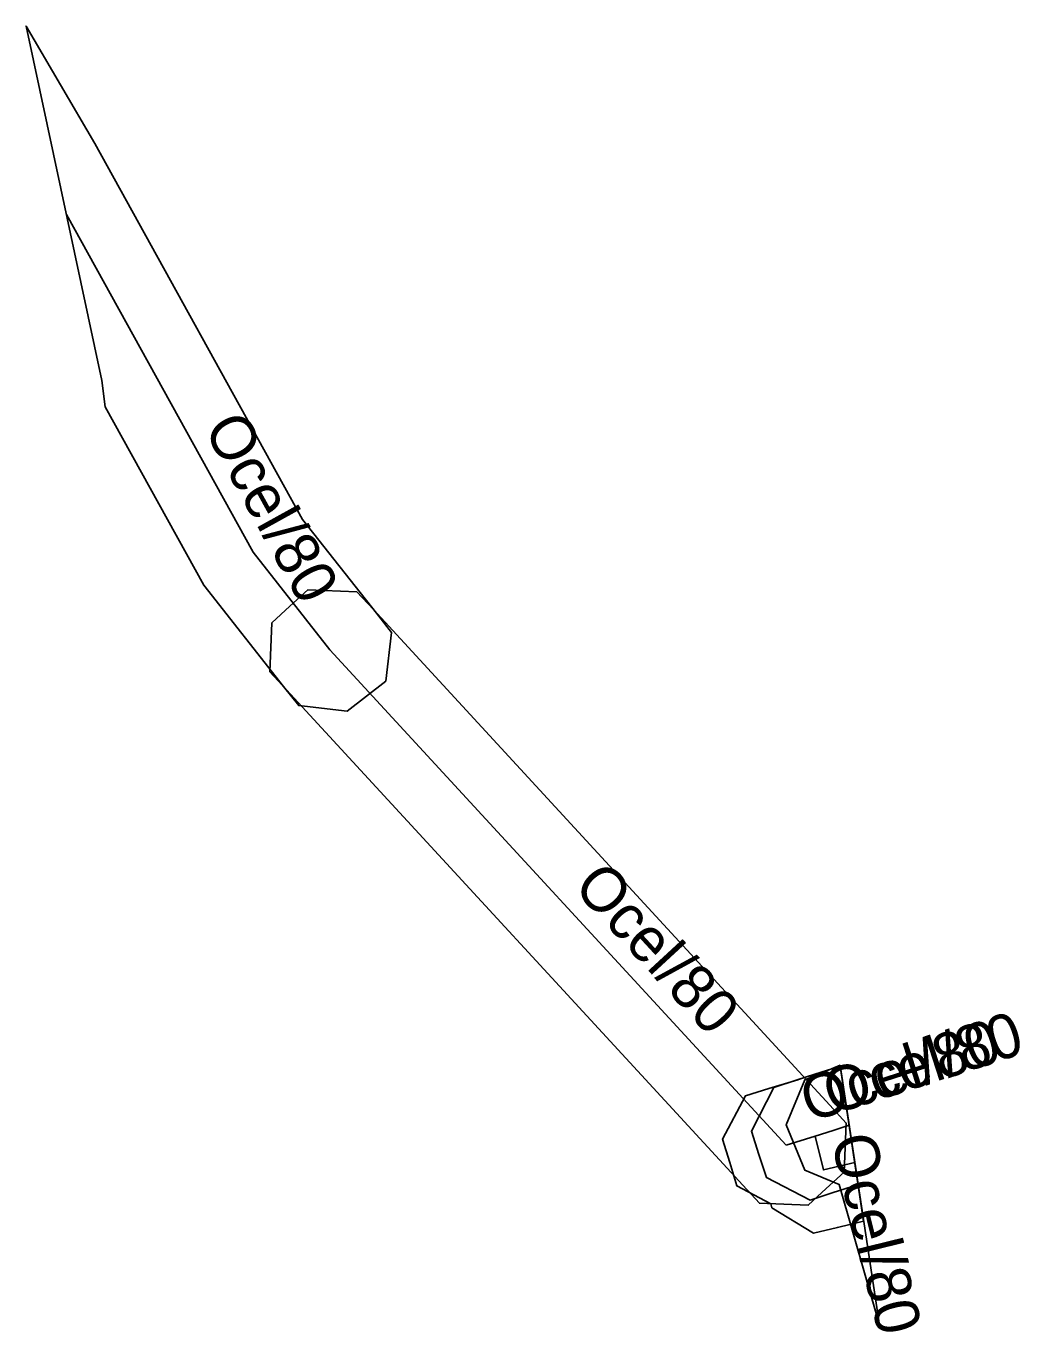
# Model space of a CAD drawing. Extents: x -569518 to -569136, y -1179473 to -1178304.
# Drawn here: x -569153.14 to -569136.31, y -1178325.81 to -1178303.7 of the extents above; entities that cross this region are included whole.
import ezdxf

# ---------------------------------------------------------------- set-up
doc = ezdxf.new("R2010")
doc.units = 0
for name, color, linetype in [('1', 7, 'Continuous'), ('24', 7, 'Continuous'), ('30', 7, 'Continuous')]:
    doc.layers.add(name, color=color, linetype=linetype)

msp = doc.modelspace()

# ---------------------------------------------------------------- linework, layer by layer
at = {"layer": '1'}
for points in [[(-569151.859, -1178309.697), (-569153.141, -1178303.701), (-569151.981, -1178305.686), (-569148.464, -1178312.045), (-569147.215, -1178313.631), (-569146.959, -1178313.957), (-569147.056, -1178314.779), (-569147.381, -1178315.035), (-569147.707, -1178315.291), (-569148.529, -1178315.194), (-569148.785, -1178314.869), (-569150.136, -1178313.155), (-569151.803, -1178310.14)], [(-569147.545, -1178313.268), (-569147.265, -1178313.572), (-569139.545, -1178321.952), (-569139.264, -1178322.257), (-569139.298, -1178323.085), (-569139.602, -1178323.365), (-569139.907, -1178323.646), (-569140.735, -1178323.612), (-569141.015, -1178323.308), (-569148.735, -1178314.928), (-569149.016, -1178314.623), (-569148.982, -1178313.795), (-569148.678, -1178313.515), (-569148.373, -1178313.234)], [(-569139.368, -1178321.293), (-569138.971, -1178323.915), (-569139.415, -1178324.022), (-569139.817, -1178324.119), (-569140.523, -1178323.69), (-569140.539, -1178323.624), (-569141.115, -1178323.319), (-569141.236, -1178322.923), (-569141.357, -1178322.527), (-569140.969, -1178321.795), (-569140.573, -1178321.674), (-569140.083, -1178321.524), (-569140.053, -1178321.515), (-569139.795, -1178321.431), (-569139.507, -1178321.338)], [(-569139.4, -1178321.304), (-569139.363, -1178321.323), (-569139.064, -1178323.297), (-569139.182, -1178323.335), (-569139.484, -1178323.432), (-569139.878, -1178323.559), (-569140.615, -1178323.18), (-569140.742, -1178322.786), (-569140.869, -1178322.392), (-569140.49, -1178321.655), (-569140.096, -1178321.528), (-569139.794, -1178321.431)], [(-569139.581, -1178321.365), (-569139.37, -1178321.278), (-569138.704, -1178325.676), (-569139.383, -1178323.297), (-569139.967, -1178323.054), (-569140.125, -1178322.671), (-569140.282, -1178322.288), (-569139.964, -1178321.523)]]:
    msp.add_lwpolyline(points, close=True, dxfattribs=at)
at = {"layer": '24'}
for points in [[(-569152.46, -1178306.885), (-569149.3, -1178312.6), (-569148, -1178314.25)], [(-569148, -1178314.25), (-569140.28, -1178322.63)], [(-569139.488, -1178322.383), (-569139.79, -1178322.48)], [(-569139.488, -1178322.383), (-569139.216, -1178322.295)], [(-569139.121, -1178322.922), (-569139.65, -1178323.05), (-569139.79, -1178322.48), (-569140.28, -1178322.63)]]:
    msp.add_lwpolyline(points, dxfattribs=at)

# ---------------------------------------------------------------- texts
at = {"layer": '30'}
for rotation, p in [(298.9408, (-569150.148, -1178310.506)), (312.6525, (-569143.906, -1178318.277)), (17.8961, (-569139.504, -1178322.124)), (17.8066, (-569139.887, -1178322.247)), (283.7995, (-569139.528, -1178322.532))]:
    msp.add_text('Ocel/80', height=0.75, rotation=rotation, dxfattribs=at).set_placement(p)

doc.saveas('drawing.dxf')
